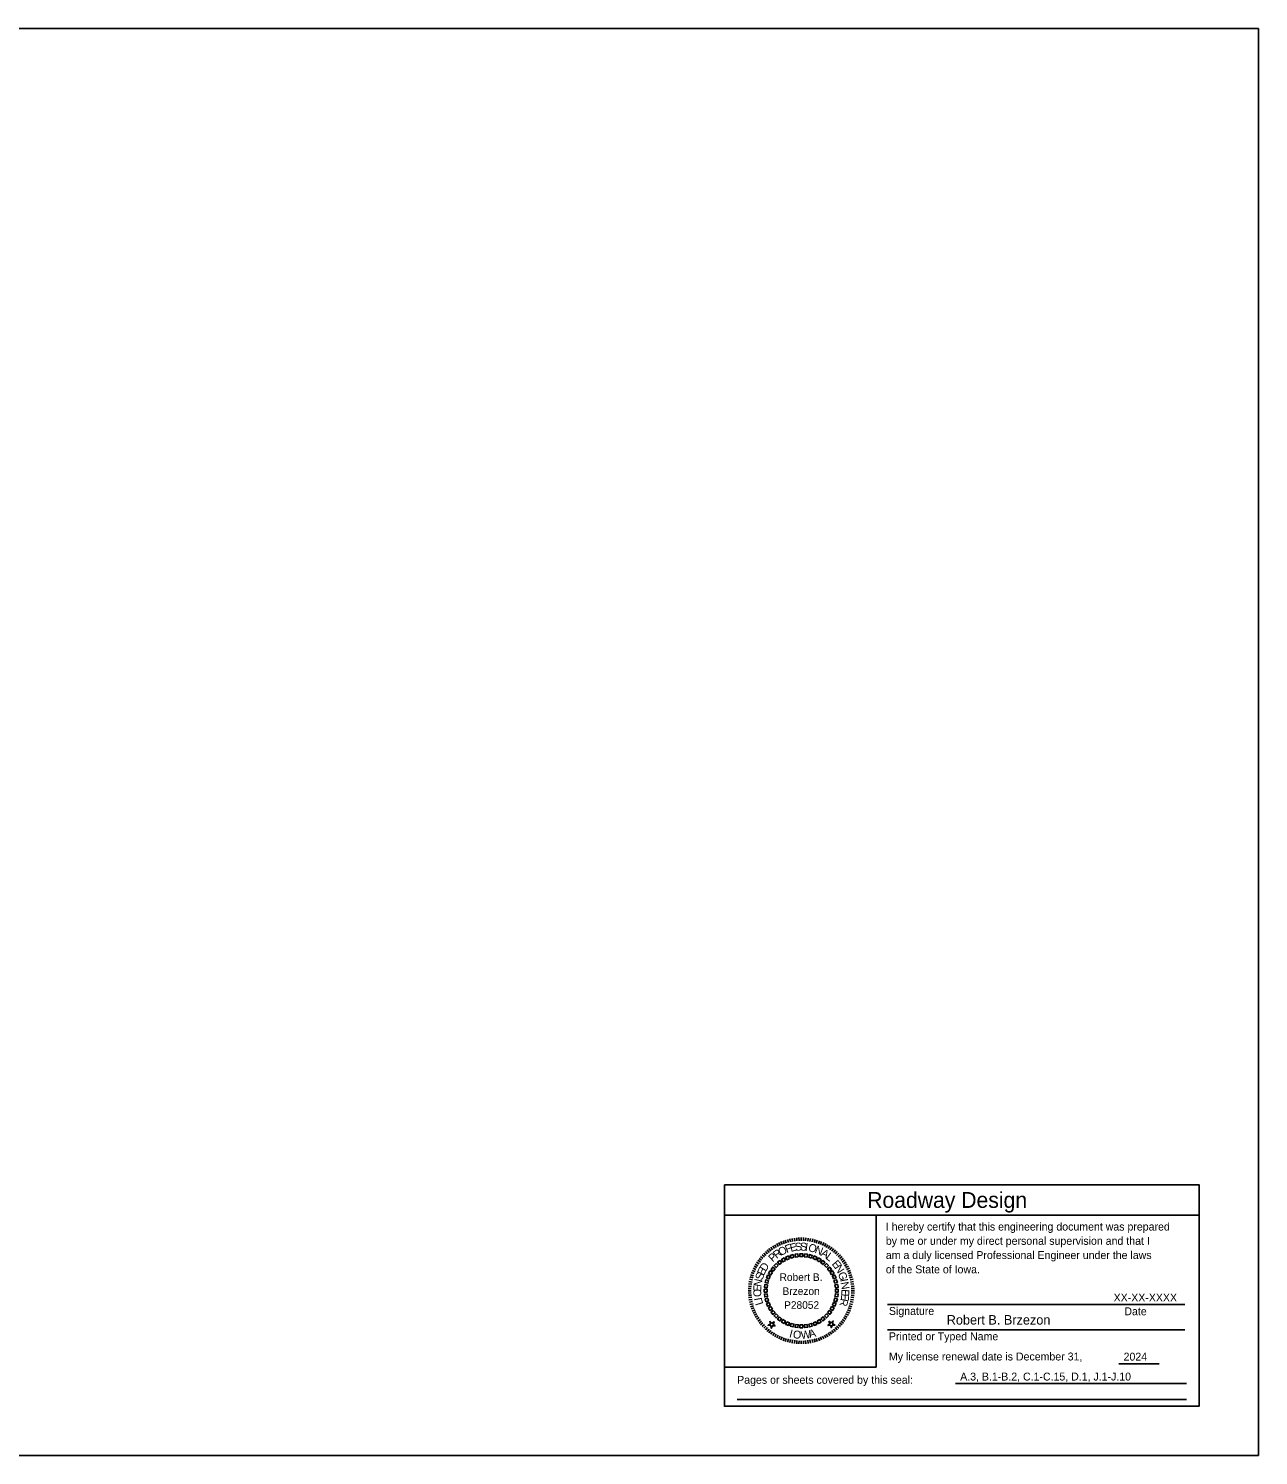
# Model space of a CAD drawing. Extents: x 10133 to 81668, y 7924 to 11018.
# Drawn here: x 11526 to 13268, y 7924 to 9944 of the extents above; entities that cross this region are included whole.
import ezdxf

# ---------------------------------------------------------------- set-up
doc = ezdxf.new("R2010")
doc.units = 0
for name, color, linetype in [('Level 1', 7, 'Continuous'), ('Level 20', 7, 'Continuous'), ('Level 21', 7, 'Continuous'), ('Level 22', 7, 'Continuous'), ('Level 4', 7, 'Continuous'), ('SheetBorder', 7, 'Continuous'), ('SheetText', 7, 'Continuous')]:
    doc.layers.add(name, color=color, linetype=linetype)

msp = doc.modelspace()

# ---------------------------------------------------------------- linework, layer by layer
at = {"layer": 'Level 20'}
msp.add_lwpolyline([(12511.5, 8307.2), (13183.4, 8307.2), (13183.4, 7993.7), (12511.5, 7993.7)], close=True, dxfattribs=at)
at = {"layer": 'Level 21'}
for p, q in [((12511.5, 8264.2), (13183.4, 8264.2)), ((12726.5, 8049.2), (12726.5, 8264.2)), ((12511.5, 8049.2), (12726.5, 8049.2))]:
    msp.add_line(p, q, dxfattribs=at)
msp.add_lwpolyline([(12511.5, 8307.2), (13183.4, 8307.2), (13183.4, 7993.7), (12511.5, 7993.7)], close=True, dxfattribs=at)
at = {"layer": 'Level 22'}
for p, q in [((13163.3, 8137.7), (12742.3, 8137.7)), ((13163.3, 8101.9), (12742.3, 8101.9)), ((13126.9, 8053.9), (13069.7, 8053.9)), ((12838.5, 8025.7), (13165.5, 8025.7)), ((12529.5, 8003.3), (13165.5, 8003.3))]:
    msp.add_line(p, q, dxfattribs=at)
at = {"layer": 'Level 4'}
for p, q in [((12584.9, 8218.5), (12582.7, 8222.4)), ((12587.7, 8220), (12585.6, 8224)), ((12590.4, 8221.3), (12588.5, 8225.4)), ((12593.2, 8222.6), (12591.5, 8226.7)), ((12596.1, 8223.7), (12594.6, 8227.9)), ((12599.1, 8224.7), (12597.7, 8229)), ((12602, 8225.6), (12600.9, 8229.9)), ((12605, 8226.3), (12604, 8230.7)), ((12608, 8226.9), (12607.3, 8231.3)), ((12611.1, 8227.4), (12610.5, 8231.8)), ((12614.2, 8227.7), (12613.8, 8232.2)), ((12617.2, 8227.9), (12617, 8232.4)), ((12620.3, 8228), (12620.3, 8232.5)), ((12623.4, 8227.9), (12623.6, 8232.4)), ((12626.5, 8227.7), (12626.9, 8232.2)), ((12629.6, 8227.4), (12630.2, 8231.8)), ((12632.6, 8226.9), (12633.4, 8231.3)), ((12635.6, 8226.3), (12636.6, 8230.7)), ((12638.6, 8225.6), (12639.8, 8229.9)), ((12641.6, 8224.7), (12643, 8229)), ((12644.5, 8223.7), (12646.1, 8227.9)), ((12647.4, 8222.6), (12649.1, 8226.7)), ((12650.2, 8221.3), (12652.1, 8225.4)), ((12653, 8220), (12655.1, 8224)), ((12655.7, 8218.5), (12658, 8222.4)), ((12564.2, 8200.3), (12560.6, 8203)), ((12566.1, 8202.7), (12562.7, 8205.6)), ((12568.2, 8205), (12564.9, 8208)), ((12570.3, 8207.3), (12567.1, 8210.4)), ((12572.5, 8209.4), (12569.5, 8212.7)), ((12574.8, 8211.4), (12572, 8214.9)), ((12577.2, 8213.4), (12574.5, 8216.9)), ((12579.7, 8215.2), (12577.2, 8218.9)), ((12582.3, 8216.9), (12579.9, 8220.7)), ((12658.4, 8216.9), (12660.8, 8220.7)), ((12660.9, 8215.2), (12663.5, 8218.8)), ((12663.4, 8213.4), (12666.1, 8216.9)), ((12665.8, 8211.4), (12668.7, 8214.9)), ((12668.1, 8209.4), (12671.2, 8212.7)), ((12670.4, 8207.3), (12673.5, 8210.4)), ((12672.5, 8205), (12675.8, 8208)), ((12674.5, 8202.7), (12678, 8205.6)), ((12676.5, 8200.3), (12680, 8203)), ((12553.8, 8181.4), (12549.6, 8182.9)), ((12554.9, 8184.3), (12550.8, 8186)), ((12556.2, 8187.1), (12552.1, 8189)), ((12557.6, 8189.9), (12553.6, 8192)), ((12559, 8192.6), (12555.2, 8194.8)), ((12560.6, 8195.2), (12556.9, 8197.6)), ((12562.4, 8197.8), (12558.7, 8200.4)), ((12678.3, 8197.8), (12682, 8200.4)), ((12680, 8195.2), (12683.8, 8197.6)), ((12681.6, 8192.6), (12685.5, 8194.8)), ((12683.1, 8189.9), (12687.1, 8192)), ((12684.5, 8187.1), (12688.5, 8189)), ((12685.7, 8184.3), (12689.9, 8186)), ((12686.8, 8181.4), (12691, 8182.9)), ((12549.8, 8163.4), (12545.4, 8163.8)), ((12550.2, 8166.4), (12545.7, 8167)), ((12550.6, 8169.5), (12546.2, 8170.3)), ((12551.2, 8172.5), (12546.9, 8173.5)), ((12552, 8175.5), (12547.6, 8176.7)), ((12552.8, 8178.5), (12548.6, 8179.8)), ((12687.8, 8178.5), (12692.1, 8179.8)), ((12688.7, 8175.5), (12693, 8176.7)), ((12689.4, 8172.5), (12693.8, 8173.5)), ((12690, 8169.5), (12694.4, 8170.3)), ((12690.5, 8166.4), (12694.9, 8167)), ((12690.8, 8163.4), (12695.3, 8163.8)), ((12549.6, 8157.2), (12545.1, 8157.2)), ((12549.6, 8160.3), (12545.2, 8160.5)), ((12549.6, 8154.1), (12545.2, 8153.9)), ((12549.8, 8151), (12545.4, 8150.7)), ((12550.2, 8148), (12545.7, 8147.4)), ((12550.6, 8144.9), (12546.2, 8144.1)), ((12551.2, 8141.9), (12546.9, 8140.9)), ((12689.4, 8141.9), (12693.8, 8140.9)), ((12690, 8144.9), (12694.4, 8144.1)), ((12690.5, 8148), (12694.9, 8147.4)), ((12690.8, 8151), (12695.3, 8150.6)), ((12691, 8160.3), (12695.5, 8160.5)), ((12691, 8154.1), (12695.5, 8153.9)), ((12691.1, 8157.2), (12695.6, 8157.2)), ((12552, 8138.9), (12547.6, 8137.7)), ((12552.8, 8135.9), (12548.6, 8134.6)), ((12553.8, 8133), (12549.6, 8131.5)), ((12554.9, 8130.1), (12550.8, 8128.4)), ((12556.2, 8127.3), (12552.1, 8125.4)), ((12557.6, 8124.5), (12553.6, 8122.5)), ((12559, 8121.8), (12555.2, 8119.6)), ((12681.6, 8121.8), (12685.5, 8119.6)), ((12683.1, 8124.5), (12687.1, 8122.5)), ((12684.5, 8127.3), (12688.5, 8125.4)), ((12685.7, 8130.1), (12689.9, 8128.4)), ((12686.8, 8133), (12691, 8131.5)), ((12687.8, 8135.9), (12692.1, 8134.6)), ((12688.7, 8138.9), (12693, 8137.7)), ((12560.6, 8119.2), (12556.9, 8116.8)), ((12562.4, 8116.6), (12558.7, 8114)), ((12564.2, 8114.1), (12560.6, 8111.4)), ((12566.1, 8111.7), (12562.7, 8108.8)), ((12568.2, 8109.4), (12564.8, 8106.4)), ((12570.3, 8107.2), (12567.1, 8104)), ((12572.5, 8105), (12569.5, 8101.7)), ((12574.8, 8103), (12572, 8099.6)), ((12577.2, 8101.1), (12574.5, 8097.5)), ((12663.4, 8101.1), (12666.1, 8097.5)), ((12665.8, 8103), (12668.7, 8099.6)), ((12668.1, 8105), (12671.2, 8101.7)), ((12670.4, 8107.2), (12673.5, 8104)), ((12672.5, 8109.4), (12675.8, 8106.4)), ((12674.5, 8111.7), (12678, 8108.8)), ((12676.5, 8114.1), (12680, 8111.4)), ((12678.3, 8116.6), (12682, 8114)), ((12680, 8119.2), (12683.8, 8116.8)), ((12579.7, 8099.2), (12577.2, 8095.6)), ((12582.3, 8097.5), (12579.9, 8093.7)), ((12584.9, 8095.9), (12582.7, 8092)), ((12587.7, 8094.4), (12585.6, 8090.5)), ((12590.4, 8093.1), (12588.5, 8089)), ((12593.2, 8091.8), (12591.5, 8087.7)), ((12596.1, 8090.7), (12594.6, 8086.5)), ((12599, 8089.7), (12597.7, 8085.4)), ((12602, 8088.9), (12600.9, 8084.5)), ((12605, 8088.1), (12604, 8083.7)), ((12608, 8087.5), (12607.3, 8083.1)), ((12611.1, 8087), (12610.5, 8082.6)), ((12614.2, 8086.7), (12613.8, 8082.2)), ((12617.2, 8086.5), (12617, 8082)), ((12620.3, 8086.4), (12620.3, 8082)), ((12623.4, 8086.5), (12623.6, 8082)), ((12626.5, 8086.7), (12626.9, 8082.2)), ((12629.6, 8087), (12630.2, 8082.6)), ((12632.6, 8087.5), (12633.4, 8083.1)), ((12635.6, 8088.1), (12636.6, 8083.7)), ((12638.6, 8088.9), (12639.8, 8084.5)), ((12641.6, 8089.7), (12643, 8085.4)), ((12644.5, 8090.7), (12646.1, 8086.5)), ((12647.4, 8091.8), (12649.1, 8087.7)), ((12650.2, 8093.1), (12652.1, 8089)), ((12653, 8094.4), (12655.1, 8090.5)), ((12655.7, 8095.9), (12658, 8092)), ((12658.4, 8097.5), (12660.8, 8093.7)), ((12660.9, 8099.2), (12663.5, 8095.6))]:
    msp.add_line(p, q, dxfattribs=at)
for points in [[(12597.9, 8200.1), (12594.4, 8198.1), (12592.4, 8201.6), (12595.9, 8203.6)], [(12603.7, 8202.7), (12600, 8201.1), (12598.4, 8204.9), (12602.1, 8206.4)], [(12609.8, 8204.5), (12605.9, 8203.4), (12604.8, 8207.3), (12608.7, 8208.4)], [(12616, 8205.4), (12612, 8204.9), (12611.5, 8208.9), (12615.5, 8209.4)], [(12622.3, 8205.6), (12618.3, 8205.6), (12618.3, 8209.6), (12622.3, 8209.6)], [(12628.6, 8204.9), (12624.6, 8205.4), (12625.2, 8209.4), (12629.2, 8208.9)], [(12634.8, 8203.4), (12630.9, 8204.5), (12631.9, 8208.4), (12635.8, 8207.3)], [(12640.7, 8201.1), (12637, 8202.7), (12638.5, 8206.4), (12642.2, 8204.9)], [(12646.3, 8198.1), (12642.8, 8200.1), (12644.8, 8203.6), (12648.3, 8201.6)], [(12579.4, 8183.1), (12577.4, 8179.6), (12573.9, 8181.7), (12576, 8185.2)], [(12583.2, 8188.3), (12580.7, 8185.1), (12577.5, 8187.5), (12580, 8190.7)], [(12587.5, 8192.8), (12584.7, 8190), (12581.8, 8192.8), (12584.7, 8195.7)], [(12592.5, 8196.8), (12589.3, 8194.4), (12586.8, 8197.6), (12590, 8200)], [(12651.4, 8194.4), (12648.2, 8196.8), (12650.6, 8200), (12653.8, 8197.6)], [(12656, 8190), (12653.1, 8192.8), (12656, 8195.7), (12658.8, 8192.8)], [(12659.9, 8185.1), (12657.5, 8188.3), (12660.7, 8190.7), (12663.1, 8187.5)], [(12663.2, 8179.7), (12661.2, 8183.1), (12664.7, 8185.2), (12666.7, 8181.7)], [(12572.6, 8165.5), (12572.1, 8161.5), (12568.1, 8162.1), (12568.6, 8166)], [(12574.1, 8171.7), (12573.1, 8167.8), (12569.2, 8168.8), (12570.2, 8172.7)], [(12576.4, 8177.6), (12574.9, 8173.9), (12571.1, 8175.4), (12572.7, 8179.1)], [(12665.8, 8173.9), (12664.3, 8177.6), (12668, 8179.1), (12669.5, 8175.4)], [(12667.6, 8167.8), (12666.5, 8171.7), (12670.4, 8172.7), (12671.5, 8168.8)], [(12668.6, 8161.5), (12668, 8165.5), (12672, 8166), (12672.6, 8162.1)], [(12572, 8159.2), (12572, 8155.2), (12567.9, 8155.2), (12567.9, 8159.2)], [(12572.1, 8152.9), (12572.6, 8148.9), (12568.6, 8148.4), (12568.1, 8152.4)], [(12573.1, 8146.6), (12574.1, 8142.7), (12570.2, 8141.7), (12569.2, 8145.6)], [(12666.5, 8142.7), (12667.6, 8146.6), (12671.5, 8145.6), (12670.4, 8141.7)], [(12668, 8148.9), (12668.6, 8152.9), (12672.6, 8152.4), (12672, 8148.4)], [(12668.7, 8155.2), (12668.7, 8159.2), (12672.7, 8159.2), (12672.7, 8155.2)], [(12574.9, 8140.6), (12576.4, 8136.8), (12572.7, 8135.3), (12571.1, 8139)], [(12577.4, 8134.8), (12579.4, 8131.3), (12576, 8129.3), (12573.9, 8132.8)], [(12580.7, 8129.4), (12583.2, 8126.2), (12580, 8123.7), (12577.5, 8126.9)], [(12584.7, 8124.4), (12587.5, 8121.6), (12584.7, 8118.7), (12581.8, 8121.6)], [(12653.1, 8121.6), (12656, 8124.4), (12658.8, 8121.6), (12656, 8118.7)], [(12657.5, 8126.2), (12659.9, 8129.4), (12663.1, 8126.9), (12660.7, 8123.7)], [(12661.2, 8131.3), (12663.2, 8134.8), (12666.7, 8132.8), (12664.7, 8129.3)], [(12664.3, 8136.8), (12665.8, 8140.6), (12669.5, 8139), (12668, 8135.3)], [(12575.8, 8114), (12578.6, 8111.4), (12581.9, 8113.3), (12580.4, 8109.8), (12583.2, 8107.3), (12579.4, 8107.7), (12577.9, 8104.2), (12577.1, 8107.9), (12573.3, 8108.3), (12576.6, 8110.2)], [(12589.3, 8120.1), (12592.5, 8117.6), (12590, 8114.4), (12586.8, 8116.9)], [(12594.4, 8116.3), (12597.9, 8114.3), (12595.9, 8110.8), (12592.4, 8112.8)], [(12600, 8113.3), (12603.7, 8111.7), (12602.1, 8108), (12598.4, 8109.6)], [(12605.9, 8111), (12609.8, 8110), (12608.7, 8106.1), (12604.8, 8107.1)], [(12612, 8109.5), (12616, 8109), (12615.5, 8105), (12611.5, 8105.5)], [(12618.3, 8108.8), (12622.3, 8108.8), (12622.3, 8104.8), (12618.3, 8104.8)], [(12624.6, 8109), (12628.6, 8109.5), (12629.2, 8105.5), (12625.2, 8105)], [(12630.9, 8110), (12634.8, 8111), (12635.8, 8107.1), (12631.9, 8106.1)], [(12637, 8111.7), (12640.7, 8113.3), (12642.2, 8109.6), (12638.5, 8108)], [(12642.8, 8114.3), (12646.3, 8116.3), (12648.3, 8112.8), (12644.8, 8110.8)], [(12648.2, 8117.6), (12651.4, 8120.1), (12653.8, 8116.9), (12650.6, 8114.4)], [(12659.5, 8114), (12662.7, 8112), (12665.6, 8114.4), (12664.7, 8110.7), (12667.9, 8108.7), (12664.1, 8108.4), (12663.2, 8104.7), (12661.8, 8108.3), (12658, 8108), (12660.9, 8110.4)]]:
    msp.add_lwpolyline(points, close=True, dxfattribs=at)
at = {"layer": 'SheetBorder'}
msp.add_lwpolyline([(10132.5, 9944), (13267.5, 9944), (13267.5, 7924), (10132.5, 7924)], close=True, dxfattribs=at)

# ---------------------------------------------------------------- texts
at = {"layer": 'Level 1'}
for s, p in [('Robert B.', (12589.6, 8171.1)), ('Brzezon', (12593.7, 8151.3)), ('P28052', (12596, 8131.6))]:
    msp.add_text(s, height=10.75, dxfattribs=at).set_placement(p)
at = {"layer": 'Level 4'}
for s, rotation, p in [('F', 21.7736, (12599.8, 8210.2)), ('E', 14.5823, (12605.7, 8212.1)), ('S', 7.3911, (12612, 8213.4)), ('S', 0.1998, (12618.5, 8214)), ('I', 353.0085, (12625.1, 8213.8)), ('O', 345.8172, (12629.4, 8213.5)), ('P', 43.3475, (12580, 8197.2)), ('R', 36.1562, (12585.4, 8202)), ('O', 28.9649, (12591.3, 8206)), ('N', 338.6259, (12638.5, 8211.1)), ('A', 331.4346, (12647.1, 8207.3)), ('L', 324.2434, (12654, 8203)), ('S', 72.1126, (12565.3, 8171.4)), ('E', 64.9213, (12567.2, 8177.7)), ('D', 57.7301, (12569.9, 8183.6)), ('E', 309.8608, (12662.9, 8194.8)), ('N', 302.6695, (12666.9, 8189.8)), ('G', 288.2869, (12672, 8181.8)), ('E', 86.4952, (12563.4, 8155.7)), ('N', 79.3039, (12563.5, 8162.2)), ('I', 281.0956, (12675.1, 8173)), ('N', 281.0956, (12675.9, 8168.8)), ('C', 93.6865, (12564, 8148.7)), ('I', 100.8778, (12565, 8144.5)), ('L', 108.069, (12566.7, 8138.7)), ('R', 259.086, (12676.2, 8146.9)), ('E', 266.2773, (12677, 8153.3)), ('E', 266.2773, (12677.4, 8159.7)), ('I', 345.2906, (12602.5, 8091.6)), ('O', 352.4819, (12608, 8090.3)), ('W', 6.8645, (12620.3, 8088.7)), ('A', 14.0557, (12632.3, 8090.1))]:
    msp.add_text(s, height=11.2, rotation=rotation, dxfattribs=at).set_placement(p)
at = {"layer": 'SheetText'}
for s, height, p in [('Roadway Design', 22.396, (12713.6, 8274.5)), ('I hereby certify that this engineering document was prepared', 11.198, (12740, 8242.4)), ('by me or under my direct personal supervision and that I', 11.198, (12740, 8222.2)), ('am a duly licensed Professional Engineer under the laws', 11.198, (12740, 8202.1)), ('of the State of Iowa.', 11.198, (12740, 8181.9)), ('XX-XX-XXXX', 11.18, (13062.5, 8142)), ('Signature', 11.2, (12744.4, 8123)), ('Robert B. Brzezon', 13.438, (12826.2, 8109.3)), ('Date', 11.2, (13077.7, 8122.5)), ('Printed or Typed Name', 11.198, (12744.4, 8087.1)), ('My license renewal date is December 31,', 11.198, (12744.4, 8058.5)), ('2024', 11.18, (13076.6, 8058.3)), ('A.3, B.1-B.2, C.1-C.15, D.1, J.1-J.10', 11.18, (12845.3, 8030.1)), ('Pages or sheets covered by this seal:', 11.198, (12529.5, 8025.5))]:
    msp.add_text(s, height=height, dxfattribs=at).set_placement(p)

doc.saveas('drawing.dxf')
